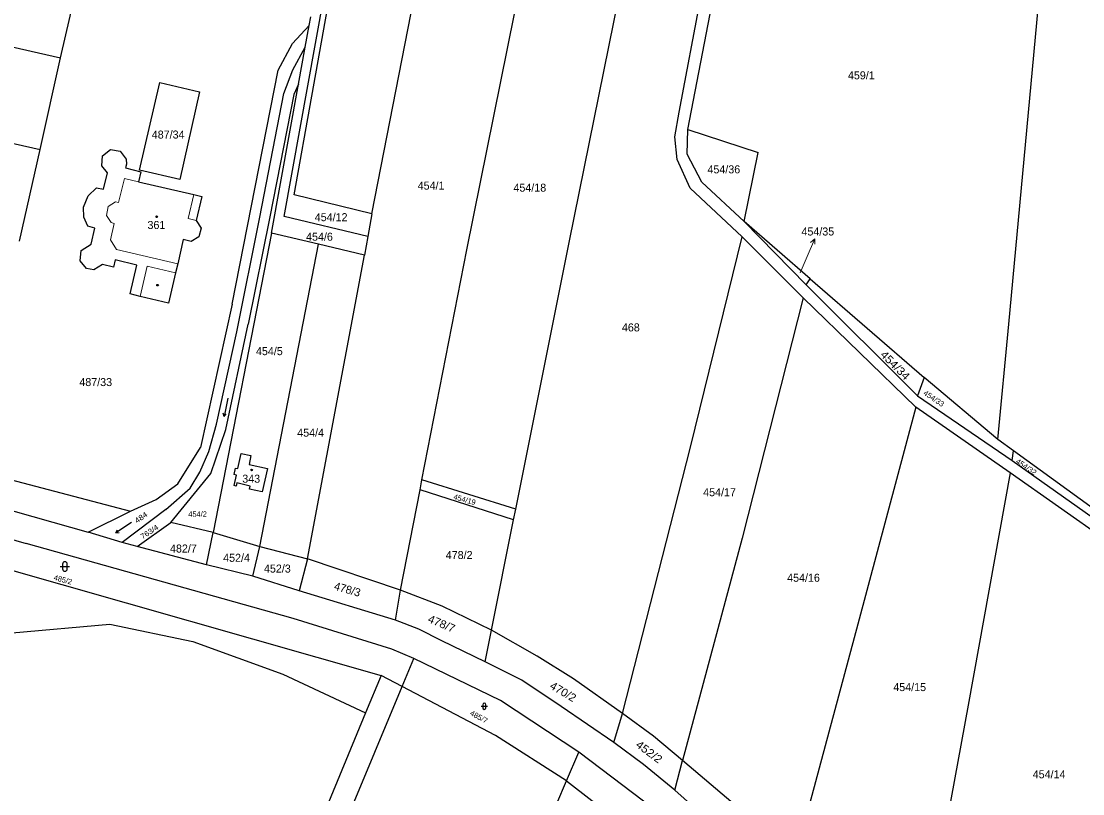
# Model space of a CAD drawing. Extents: x -701211 to -698780, y -1014269 to -1012378.
# Drawn here: x -700007.4 to -699782, y -1013365.7 to -1013201.6 of the extents above; entities that cross this region are included whole.
import ezdxf
from ezdxf.enums import TextEntityAlignment as Align

# ---------------------------------------------------------------- set-up
doc = ezdxf.new("R2010")
doc.units = 0
doc.header["$LTSCALE"] = 0.68
for name, color, linetype, lineweight in [('1', 7, 'Continuous', 25), ('3', 7, 'Continuous', 25), ('4', 7, 'Continuous', 13), ('5', 7, 'Continuous', 25), ('7', 7, 'Continuous', 13)]:
    doc.layers.add(name, color=color, linetype=linetype, lineweight=lineweight)
doc.layers.add('2', color=7, linetype='Continuous')

msp = doc.modelspace()

# ---------------------------------------------------------------- linework, layer by layer
at = {"layer": '1'}
for p, q in [((-699951.6, -1013243.11), (-699934.65, -1013149.61)), ((-699949.47, -1013238.52), (-699933.68, -1013149.86)), ((-699890.97, -1013248.25), (-699873.43, -1013161.36)), ((-699867.72, -1013220.92), (-699856.49, -1013161.78)), ((-699999.07, -1013209.38), (-699994.57, -1013189.81)), ((-699932.97, -1013242.57), (-699923.22, -1013192.74)), ((-700044.62, -1013199.1), (-699999.07, -1013209.38)), ((-699865.88, -1013224.66), (-699860.76, -1013198.23)), ((-699797.7, -1013265.97), (-699791.49, -1013198.92)), ((-699946.3, -1013202.54), (-699945.96, -1013200.72)), ((-699949.83, -1013206.36), (-699946.3, -1013202.54)), ((-699947.13, -1013207.13), (-699946.3, -1013202.54)), ((-699949.75, -1013211.96), (-699947.13, -1013207.13)), ((-699948.55, -1013214.97), (-699947.13, -1013207.13)), ((-700003.42, -1013228.88), (-699999.07, -1013209.38)), ((-699951.66, -1013217.01), (-699949.75, -1013211.96)), ((-699982.32, -1013233.27), (-699978, -1013214.63)), ((-699978, -1013214.63), (-699969.57, -1013216.64)), ((-699954.27, -1013246.67), (-699948.55, -1013214.97)), ((-699948.55, -1013214.97), (-699949.58, -1013217.18)), ((-699969.57, -1013216.64), (-699973.78, -1013235.23)), ((-699956.76, -1013243.24), (-699951.66, -1013217.01)), ((-699949.58, -1013217.18), (-699954.63, -1013243.16)), ((-700049.02, -1013218.61), (-700003.42, -1013228.88)), ((-699868.64, -1013226.22), (-699867.72, -1013220.92)), ((-699866.01, -1013229.86), (-699865.88, -1013224.66)), ((-699865.88, -1013224.66), (-699850.93, -1013229.5)), ((-699868.14, -1013231.02), (-699868.64, -1013226.22)), ((-700007.83, -1013248.37), (-700003.42, -1013228.88)), ((-699990.15, -1013230.22), (-699988.49, -1013228.89)), ((-699988.49, -1013228.89), (-699986.42, -1013229.23)), ((-699990.32, -1013232.33), (-699990.15, -1013230.22)), ((-699986.42, -1013229.23), (-699985.17, -1013230.9)), ((-699985.17, -1013230.9), (-699985.12, -1013231.97)), ((-699865.36, -1013237.08), (-699868.14, -1013231.02)), ((-699862.92, -1013235.83), (-699866.01, -1013229.86)), ((-699853.89, -1013244.21), (-699850.93, -1013229.5)), ((-699989.11, -1013233.83), (-699990.32, -1013232.33)), ((-699985.12, -1013231.97), (-699985.3, -1013232.77)), ((-699985.3, -1013232.77), (-699982.07, -1013233.59)), ((-699982.07, -1013233.59), (-699982.57, -1013235.72)), ((-699973.78, -1013235.23), (-699982.32, -1013233.27)), ((-699989.94, -1013237.32), (-699989.11, -1013233.83)), ((-699982.57, -1013235.72), (-699970.8, -1013238.44)), ((-699853.89, -1013244.21), (-699862.92, -1013235.83)), ((-699993.25, -1013238.75), (-699991.43, -1013236.99)), ((-699991.43, -1013236.99), (-699989.94, -1013237.32)), ((-699854.34, -1013247.43), (-699865.36, -1013237.08)), ((-699994.21, -1013241.14), (-699993.25, -1013238.75)), ((-699970.8, -1013238.44), (-699969.12, -1013238.88)), ((-699969.12, -1013238.88), (-699970.28, -1013243.97)), ((-699932.97, -1013242.57), (-699949.47, -1013238.52)), ((-699994.16, -1013243.23), (-699994.21, -1013241.14)), ((-699932.97, -1013242.57), (-699933.85, -1013247.39)), ((-699993.32, -1013245.2), (-699994.16, -1013243.23)), ((-699970.28, -1013243.97), (-699969.25, -1013245.6)), ((-699961.66, -1013267.61), (-699956.76, -1013243.24)), ((-699954.63, -1013243.16), (-699959.22, -1013265.97)), ((-699933.85, -1013247.39), (-699951.6, -1013243.11)), ((-699853.89, -1013244.21), (-699840.75, -1013257.63)), ((-699991.83, -1013245.56), (-699993.32, -1013245.2)), ((-699992.59, -1013248.98), (-699991.83, -1013245.56)), ((-699969.25, -1013245.6), (-699969.7, -1013247.44)), ((-699954.27, -1013246.67), (-699966.7, -1013310.26)), ((-699944.3, -1013249.02), (-699954.27, -1013246.67)), ((-699994.68, -1013250.37), (-699992.59, -1013248.98)), ((-699973.04, -1013248.03), (-699974.21, -1013253.16)), ((-699971.35, -1013248.43), (-699973.04, -1013248.03)), ((-699969.7, -1013247.44), (-699971.35, -1013248.43)), ((-699956.79, -1013313.2), (-699944.3, -1013249.02)), ((-699934.57, -1013251.32), (-699944.3, -1013249.02)), ((-699933.85, -1013247.39), (-699934.57, -1013251.32)), ((-699902.41, -1013305.3), (-699890.97, -1013248.25)), ((-699865.28, -1013292.1), (-699854.34, -1013247.43)), ((-699841.39, -1013260.39), (-699854.34, -1013247.43)), ((-699994.96, -1013252.53), (-699994.68, -1013250.37)), ((-699946.62, -1013315.85), (-699934.57, -1013251.32)), ((-699922.34, -1013299.07), (-699912.82, -1013250.16)), ((-699993.61, -1013254.16), (-699994.96, -1013252.53)), ((-699990.19, -1013253.32), (-699992.04, -1013254.44)), ((-699987.85, -1013253.86), (-699990.19, -1013253.32)), ((-699987.48, -1013252.34), (-699987.85, -1013253.86)), ((-699982.88, -1013253.42), (-699987.48, -1013252.34)), ((-699984.3, -1013259.56), (-699982.88, -1013253.42)), ((-699974.21, -1013253.16), (-699974.66, -1013255.06)), ((-699992.04, -1013254.44), (-699993.61, -1013254.16)), ((-699974.66, -1013255.06), (-699976.18, -1013261.52)), ((-699817.07, -1013281.22), (-699840.75, -1013257.63)), ((-699839.9, -1013256.32), (-699815.68, -1013277.28)), ((-699982.19, -1013260.14), (-699984.3, -1013259.56)), ((-699976.18, -1013261.52), (-699982.19, -1013260.14)), ((-699841.39, -1013260.39), (-699854.34, -1013311.46)), ((-699817.42, -1013283.61), (-699841.39, -1013260.39)), ((-699962.67, -1013261.73), (-699969.38, -1013292.18)), ((-699963.97, -1013288.37), (-699959.22, -1013265.97)), ((-699800.03, -1013290.47), (-699797.7, -1013265.97)), ((-699965.97, -1013287.26), (-699961.66, -1013267.61)), ((-699815.68, -1013277.28), (-699817.07, -1013281.22)), ((-699800.03, -1013290.47), (-699815.68, -1013277.28)), ((-699817.07, -1013281.22), (-699797.02, -1013294.95)), ((-699817.42, -1013283.61), (-699829.74, -1013329.68)), ((-699797.4, -1013297.58), (-699817.42, -1013283.61)), ((-699967.59, -1013293), (-699965.97, -1013287.26)), ((-699967.21, -1013297.73), (-699963.97, -1013288.37)), ((-700057.06, -1013292.27), (-699993.2, -1013310.15)), ((-699974.19, -1013299.92), (-699969.38, -1013292.18)), ((-699879.75, -1013348.72), (-699865.28, -1013292.1)), ((-699796.74, -1013292.89), (-699800.03, -1013290.47)), ((-699969.5, -1013297.41), (-699967.59, -1013293)), ((-699961.43, -1013296.65), (-699960.75, -1013293.43)), ((-699960.75, -1013293.43), (-699958.68, -1013293.9)), ((-699958.68, -1013293.9), (-699959.02, -1013295.78)), ((-699797.02, -1013294.95), (-699796.74, -1013292.89)), ((-699772.08, -1013310.79), (-699796.74, -1013292.89)), ((-700018.71, -1013296.65), (-699984.23, -1013305.69)), ((-699962.21, -1013297.94), (-699961.92, -1013296.55)), ((-699961.92, -1013296.55), (-699961.43, -1013296.65)), ((-699959.02, -1013295.78), (-699955.15, -1013296.64)), ((-699955.15, -1013296.64), (-699956.24, -1013301.63)), ((-699797.02, -1013294.95), (-699768.4, -1013315.19)), ((-700057.45, -1013297.95), (-700006.41, -1013312.57)), ((-699975.65, -1013308.14), (-699967.21, -1013297.73)), ((-699971.56, -1013300.79), (-699969.5, -1013297.41)), ((-699961.72, -1013298.04), (-699962.21, -1013297.94)), ((-699962.19, -1013300.27), (-699961.72, -1013298.04)), ((-699922.75, -1013301.16), (-699922.34, -1013299.07)), ((-699902.41, -1013305.3), (-699922.34, -1013299.07)), ((-699797.4, -1013297.58), (-699806.32, -1013346.89)), ((-699763.06, -1013321.76), (-699797.4, -1013297.58)), ((-699978.8, -1013303.21), (-699974.19, -1013299.92)), ((-699976.75, -1013305.35), (-699971.56, -1013300.79)), ((-699961.82, -1013300.38), (-699962.19, -1013300.27)), ((-699961.66, -1013299.67), (-699961.82, -1013300.38)), ((-699958.8, -1013300.38), (-699961.66, -1013299.67)), ((-699958.94, -1013301.06), (-699958.8, -1013300.38)), ((-699956.24, -1013301.63), (-699958.94, -1013301.06)), ((-699926.9, -1013322.52), (-699922.75, -1013301.16)), ((-699902.87, -1013307.58), (-699922.75, -1013301.16)), ((-699984.23, -1013305.69), (-699978.8, -1013303.21)), ((-700058.42, -1013304.32), (-699931, -1013340.6)), ((-699993.2, -1013310.15), (-699984.23, -1013305.69)), ((-699976.75, -1013305.35), (-699985.99, -1013312.35)), ((-699902.87, -1013307.58), (-699902.41, -1013305.3)), ((-699907.56, -1013330.99), (-699902.87, -1013307.58)), ((-699985.99, -1013312.35), (-699993.2, -1013310.15)), ((-699982.85, -1013313.19), (-699975.65, -1013308.14)), ((-699966.7, -1013310.26), (-699975.65, -1013308.14)), ((-699968.13, -1013317.11), (-699966.7, -1013310.26)), ((-699966.7, -1013310.26), (-699956.79, -1013313.2)), ((-699949.66, -1013328.49), (-700006.41, -1013312.57)), ((-699982.85, -1013313.19), (-699985.99, -1013312.35)), ((-699854.34, -1013311.46), (-699867, -1013358.7)), ((-699968.13, -1013317.11), (-699982.85, -1013313.19)), ((-699958.26, -1013319.55), (-699956.79, -1013313.2)), ((-699956.79, -1013313.2), (-699946.62, -1013315.85)), ((-699958.26, -1013319.55), (-699968.13, -1013317.11)), ((-699946.62, -1013315.85), (-699948.43, -1013322.65)), ((-699948.43, -1013322.65), (-699958.26, -1013319.55)), ((-699927.95, -1013328.87), (-699948.43, -1013322.65)), ((-699918.06, -1013325.86), (-699926.9, -1013322.52)), ((-699907.56, -1013330.99), (-699918.06, -1013325.86)), ((-700009.39, -1013331.54), (-699988.62, -1013329.74)), ((-699988.62, -1013329.74), (-699970.99, -1013333.43)), ((-699928.71, -1013335.06), (-699949.66, -1013328.49)), ((-699922.97, -1013330.8), (-699927.95, -1013328.87)), ((-699829.74, -1013329.68), (-699843.69, -1013381.39)), ((-699918.1, -1013333.23), (-699922.97, -1013330.8)), ((-699908.95, -1013337.69), (-699907.56, -1013330.99)), ((-699897.9, -1013336.53), (-699907.56, -1013330.99)), ((-699970.99, -1013333.43), (-699951.92, -1013340.36)), ((-699924.08, -1013336.98), (-699928.71, -1013335.06)), ((-699908.95, -1013337.69), (-699918.1, -1013333.23)), ((-699926.55, -1013342.94), (-699924.08, -1013336.98)), ((-699905.68, -1013345.95), (-699924.08, -1013336.98)), ((-699890.17, -1013341.32), (-699897.9, -1013336.53)), ((-699901.14, -1013341.64), (-699908.95, -1013337.69)), ((-699951.92, -1013340.36), (-699934.3, -1013348.53)), ((-699931, -1013340.6), (-699934.3, -1013348.53)), ((-699926.55, -1013342.94), (-699931, -1013340.6)), ((-699892.74, -1013347.18), (-699901.14, -1013341.64)), ((-699879.75, -1013348.72), (-699890.17, -1013341.32)), ((-699951.32, -1013402.53), (-699926.55, -1013342.94)), ((-699906.75, -1013353.33), (-699926.55, -1013342.94)), ((-699889.02, -1013356.93), (-699905.68, -1013345.95)), ((-699934.3, -1013348.53), (-699980.25, -1013459.13)), ((-699881.57, -1013354.83), (-699892.74, -1013347.18)), ((-699806.32, -1013346.89), (-699818.01, -1013410.55)), ((-699881.57, -1013354.83), (-699879.75, -1013348.72)), ((-699873.2, -1013353.5), (-699879.75, -1013348.72)), ((-699891.63, -1013363.02), (-699906.75, -1013353.33)), ((-699875.27, -1013359.53), (-699881.57, -1013354.83)), ((-699867, -1013358.7), (-699873.2, -1013353.5)), ((-699891.63, -1013363.02), (-699889.02, -1013356.93)), ((-699869.94, -1013371.34), (-699889.02, -1013356.93)), ((-699868.6, -1013364.96), (-699875.27, -1013359.53)), ((-699868.6, -1013364.96), (-699867, -1013358.7)), ((-699853.88, -1013369.8), (-699867, -1013358.7)), ((-699893.69, -1013367.83), (-699891.63, -1013363.02)), ((-699891.63, -1013363.02), (-699881.16, -1013371.11)), ((-699856.87, -1013375.49), (-699868.6, -1013364.96))]:
    msp.add_line(p, q, dxfattribs=at)
for points in [[(-699912.82, -1013250.16), (-699898.35, -1013178.58), (-699923.22, -1013192.74)], [(-699962.67, -1013261.73), (-699952.87, -1013212.05), (-699949.83, -1013206.36)], [(-699840.75, -1013257.63), (-699839.9, -1013256.32), (-699853.89, -1013244.21)], [(-699927.95, -1013328.87), (-699926.9, -1013322.52), (-699946.62, -1013315.85)]]:
    msp.add_lwpolyline(points, dxfattribs=at)
at = {"layer": '3'}
for p, q in [((-699964.351, -1013285.623), (-699964.556, -1013284.916)), ((-699987.378, -1013310.336), (-699987.012, -1013309.698)), ((-699998.671, -1013316.961), (-699998.671, -1013317.962)), ((-699997.669, -1013317.962), (-699997.669, -1013316.961)), ((-699999.171, -1013317.461), (-699997.169, -1013317.461)), ((-699909.771, -1013347.161), (-699908.429, -1013347.161)), ((-699909.435, -1013346.825), (-699909.435, -1013347.496)), ((-699908.765, -1013347.496), (-699908.765, -1013346.825))]:
    msp.add_line(p, q, dxfattribs=at)
for points in [[(-699963.584, -1013281.677), (-699964.351, -1013285.623), (-699963.897, -1013285.045)], [(-699984.007, -1013308.147), (-699987.378, -1013310.336), (-699986.646, -1013310.261)]]:
    msp.add_lwpolyline(points, dxfattribs=at)
for centre, radius, start, end in [((-699998.17, -1013316.9609), 0.5, 0, 180), ((-699998.17, -1013317.9609), 0.5, 180, 359.98789), ((-699909.1, -1013346.8256), 0.335, 0, 180), ((-699909.1, -1013347.4956), 0.335, 180, 359.98789)]:
    msp.add_arc(centre, radius, start, end, dxfattribs=at)
at = {"layer": '4'}
for p, q in [((-699985.52, -1013235.03), (-699986.76, -1013240.15)), ((-699982.57, -1013235.72), (-699985.52, -1013235.03)), ((-699987.43, -1013239.99), (-699988.96, -1013240.99)), ((-699986.76, -1013240.15), (-699987.43, -1013239.99)), ((-699971.96, -1013243.56), (-699970.8, -1013238.44)), ((-699988.96, -1013240.99), (-699989.36, -1013242.87)), ((-699989.36, -1013242.87), (-699988.37, -1013244.41)), ((-699987.73, -1013244.58), (-699988.49, -1013248.05)), ((-699988.37, -1013244.41), (-699987.73, -1013244.58)), ((-699970.28, -1013243.97), (-699971.96, -1013243.56)), ((-699988.49, -1013248.05), (-699987.2, -1013250.14)), ((-699987.2, -1013250.14), (-699974.21, -1013253.16)), ((-699982.19, -1013260.14), (-699980.7, -1013253.63)), ((-699980.7, -1013253.63), (-699974.66, -1013255.06))]:
    msp.add_line(p, q, dxfattribs=at)
at = {"layer": '5'}
for centre in [(-699978.6868, -1013243.1692), (-699978.4968, -1013257.6992), (-699958.5168, -1013296.9592)]:
    msp.add_circle(centre, 0.175, dxfattribs=at)
at = {"layer": '7'}
msp.add_line((-699838.937, -1013247.888), (-699839.79, -1013248.614), dxfattribs=at)
msp.add_lwpolyline([(-699841.99, -1013255.1), (-699840.11, -1013250.65), (-699838.937, -1013247.888), (-699838.868, -1013249.005)], dxfattribs=at)

# ---------------------------------------------------------------- texts
at = {"layer": '2'}
for s, height, p in [('459/1', 1.7, (-699829.03, -1013213.975)), ('454/36', 1.7, (-699858.23, -1013233.945)), ('454/1', 1.7, (-699920.4, -1013237.405)), ('454/18', 1.7, (-699899.43, -1013237.835)), ('468', 1.7, (-699877.979, -1013267.525)), ('454/17', 1.7, (-699859.14, -1013302.535)), ('454/2', 1.14, (-699969.989, -1013306.895)), ('482/7', 1.7, (-699973, -1013314.495)), ('478/2', 1.7, (-699914.44, -1013315.875)), ('454/16', 1.7, (-699841.31, -1013320.705)), ('454/15', 1.7, (-699818.76, -1013343.935)), ('454/14', 1.7, (-699789.15, -1013362.455))]:
    msp.add_text(s, height=height, dxfattribs=at).set_placement(p, align=Align.CENTER)
for s, p in [('487/34', (-699979.72, -1013226.555)), ('454/12', (-699945.1, -1013244.105)), ('361', (-699980.63, -1013245.765)), ('454/6', (-699946.95, -1013248.255)), ('454/35', (-699841.74, -1013247.145)), ('454/5', (-699957.59, -1013272.565)), ('487/33', (-699995.1, -1013279.135)), ('454/4', (-699948.83, -1013289.885)), ('343', (-699960.5, -1013299.665)), ('452/4', (-699964.56, -1013316.465)), ('452/3', (-699955.89, -1013318.755))]:
    msp.add_text(s, height=1.7, dxfattribs=at).set_placement(p)
for s, height, rotation, width, p in [('454/34', 1.7, 315, 1.1, (-699822.4435, -1013275.3265)), ('454/33', 1.14, 326, 1.05, (-699813.9367, -1013282.2452)), ('454/32', 1.14, 326, 1.05, (-699794.3267, -1013296.7752)), ('484', 1.14, 35, 1.15, (-699981.6699, -1013307.5162)), ('763/4', 1.14, 33, 1.1, (-699979.9059, -1013310.5756)), ('478/7', 1.7, 337, 1.05, (-699918.4961, -1013330.383)), ('470/2', 1.7, 329, 1.05, (-699892.7953, -1013344.7875)), ('485/7', 1.14, 331, 1.05, (-699910.5168, -1013349.9071)), ('452/2', 1.7, 323, 1.1, (-699874.6045, -1013357.5151))]:
    msp.add_text(s, height=height, rotation=rotation, dxfattribs=dict(at, width=width)).set_placement(p, align=Align.CENTER)
for s, height, rotation, p in [('454/19', 1.14, 344, (-699913.4286, -1013303.7966)), ('485/2', 1.14, 345, (-699998.7375, -1013320.8154)), ('478/3', 1.7, 344, (-699938.4078, -1013323.1319))]:
    msp.add_text(s, height=height, rotation=rotation, dxfattribs=at).set_placement(p, align=Align.CENTER)

doc.saveas('drawing.dxf')
